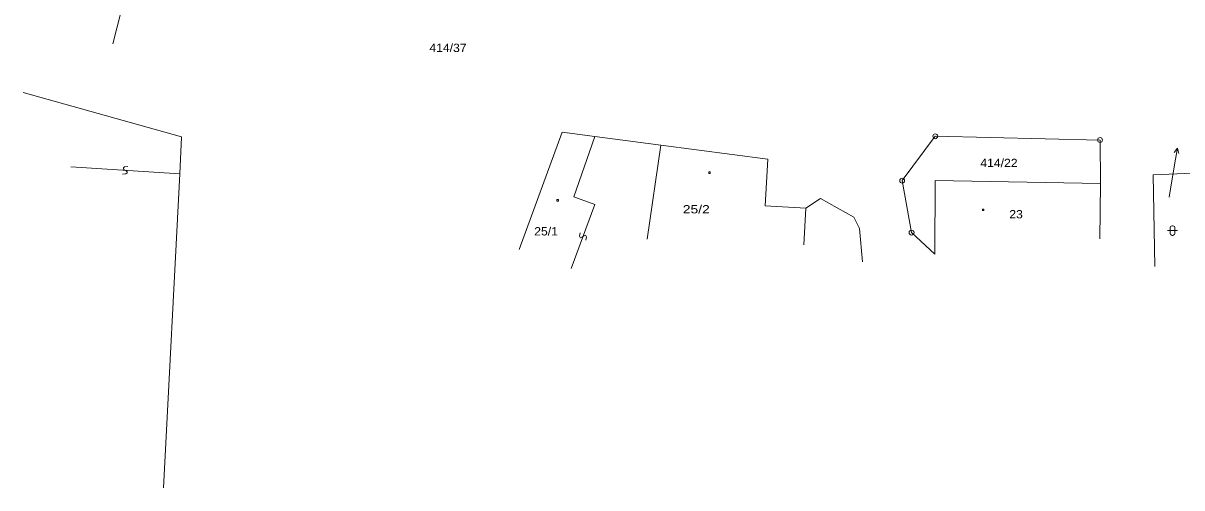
# Model space of a CAD drawing. Extents: x -736847 to -736508, y -1028413 to -1028271.
# Drawn here: x -736721.1 to -736602.3, y -1028413.2 to -1028365.6 of the extents above; entities that cross this region are included whole.
import ezdxf
from ezdxf.enums import TextEntityAlignment as Align

# ---------------------------------------------------------------- set-up
doc = ezdxf.new("R2010")
doc.units = 0
doc.header["$LTSCALE"] = 0.2
doc.layers.add('1', color=7, linetype='Continuous', lineweight=13)
doc.layers.add('2', color=7, linetype='Continuous', lineweight=13)

msp = doc.modelspace()

# ---------------------------------------------------------------- linework, layer by layer
at = {"layer": '1'}
for p, q in [((-736707.02, -1028348.65), (-736711.92, -1028367.73)), ((-736721.11, -1028372.69), (-736704.87, -1028377.24)), ((-736704.87, -1028377.24), (-736705.06, -1028381.04)), ((-736655.7, -1028378.1), (-736644.73, -1028379.54)), ((-736644.73, -1028379.54), (-736645.01, -1028384.31)), ((-736705.06, -1028381.04), (-736716.23, -1028380.33)), ((-736603.59, -1028383.42), (-736602.99, -1028379.9)), ((-736705.06, -1028381.04), (-736706.73, -1028413.24)), ((-736610.7, -1028387.72), (-736610.64, -1028382.05)), ((-736601.16, -1028380.99), (-736605.21, -1028381.16)), ((-736605.06, -1028390.55), (-736605.21, -1028381.16)), ((-736645.01, -1028384.31), (-736640.86, -1028384.55)), ((-736640.86, -1028384.55), (-736641.06, -1028388.32))]:
    msp.add_line(p, q, dxfattribs=at)
for points in [[(-736670.23, -1028388.81), (-736665.84, -1028376.77), (-736662.47, -1028377.21), (-736655.7, -1028378.1), (-736657.1, -1028387.74)], [(-736662.47, -1028377.21), (-736664.64, -1028383.4), (-736662.5, -1028384.18), (-736664.9, -1028390.76)], [(-736610.64, -1028382.05), (-736610.67, -1028377.58), (-736627.57, -1028377.19), (-736630.97, -1028381.74)], [(-736627.63, -1028389.29), (-736630, -1028387.07), (-736630.97, -1028381.74)], [(-736610.64, -1028382.05), (-736627.59, -1028381.73), (-736627.63, -1028389.29)], [(-736640.86, -1028384.55), (-736639.34, -1028383.58), (-736635.91, -1028385.49), (-736635.35, -1028386.65), (-736635.02, -1028390.08)]]:
    msp.add_lwpolyline(points, dxfattribs=at)
at = {"layer": '2'}
for p, q in [((-736602.738, -1028378.421), (-736602.576, -1028378.955)), ((-736603.74, -1028386.86), (-736602.74, -1028386.86))]:
    msp.add_line(p, q, dxfattribs=at)
for points in [[(-736602.99, -1028379.9), (-736602.738, -1028378.421), (-736603.069, -1028378.872)], [(-736710.37, -1028380.301), (-736710.722, -1028380.329), (-736710.828, -1028380.422), (-736710.835, -1028380.522), (-736710.741, -1028380.628), (-736710.548, -1028380.741), (-736710.454, -1028380.847), (-736710.461, -1028380.947), (-736710.567, -1028381.04), (-736710.919, -1028381.068)], [(-736663.99, -1028387.098), (-736664.063, -1028387.444), (-736664.003, -1028387.572), (-736663.909, -1028387.606), (-736663.781, -1028387.546), (-736663.618, -1028387.393), (-736663.49, -1028387.333), (-736663.396, -1028387.367), (-736663.336, -1028387.495), (-736663.409, -1028387.841)]]:
    msp.add_lwpolyline(points, dxfattribs=at)
for points in [[(-736650.8, -1028380.85), (-736650.65, -1028380.85), (-736650.65, -1028381), (-736650.8, -1028381)], [(-736666.37, -1028383.69), (-736666.22, -1028383.69), (-736666.22, -1028383.84), (-736666.37, -1028383.84)], [(-736622.74, -1028384.67), (-736622.59, -1028384.67), (-736622.59, -1028384.82), (-736622.74, -1028384.82)], [(-736603.19, -1028387.36), (-736603.29, -1028387.36), (-736603.39, -1028387.31), (-736603.44, -1028387.26), (-736603.49, -1028387.16), (-736603.49, -1028386.56), (-736603.44, -1028386.46), (-736603.39, -1028386.41), (-736603.29, -1028386.36), (-736603.19, -1028386.36), (-736603.09, -1028386.41), (-736603.04, -1028386.46), (-736602.99, -1028386.56), (-736602.99, -1028387.16), (-736603.04, -1028387.26), (-736603.09, -1028387.31)]]:
    msp.add_lwpolyline(points, close=True, dxfattribs=at)
for centre, radius in [((-736627.57, -1028377.19), 0.25), ((-736627.57, -1028377.19), 0.005), ((-736610.67, -1028377.58), 0.25), ((-736610.67, -1028377.58), 0.005), ((-736630.97, -1028381.74), 0.25), ((-736630.97, -1028381.74), 0.005), ((-736630, -1028387.07), 0.25), ((-736630, -1028387.07), 0.005)]:
    msp.add_circle(centre, radius, dxfattribs=at)

# ---------------------------------------------------------------- texts
at = {"layer": '2', "width": 1.1}
msp.add_text('414/37', height=0.85, dxfattribs=at).set_placement((-736677.544, -1028368.55), align=Align.CENTER)
at = {"layer": '2'}
for s, height, width, p in [('414/22', 0.85, 1.1, (-736622.95, -1028380.35)), ('25/2', 0.85, 1.25, (-736653.46, -1028385.1)), ('414/8', 0.05, 1.05, (-736603.59, -1028383.42)), ('23', 0.85, 1.1, (-736619.98, -1028385.61)), ('25/1', 0.85, 1.1, (-736668.7, -1028387.36))]:
    msp.add_text(s, height=height, dxfattribs=dict(at, width=width)).set_placement(p)

doc.saveas('drawing.dxf')
